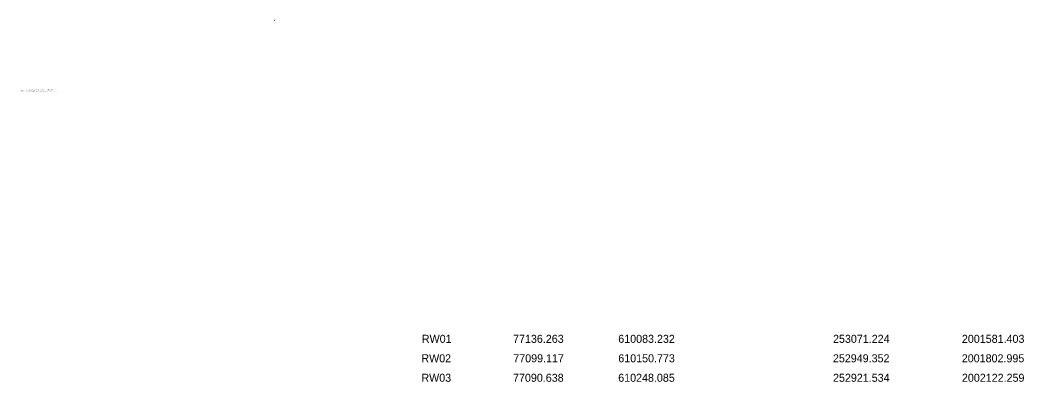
# Model space of a CAD drawing. Extents: x -4451 to 6119, y -1533 to 848.
# Drawn here: x 701 to 6119, y -1533 to 417 of the extents above; entities that cross this region are included whole.
import ezdxf

# ---------------------------------------------------------------- set-up
doc = ezdxf.new("R2010")
doc.units = 0
doc.layers.add('SC_Scratch1', color=7, linetype='Continuous')

msp = doc.modelspace()

# ---------------------------------------------------------------- linework, layer by layer
at = {"layer": 'SC_Scratch1'}
for p, q in [((2073.5, 417), (2074.5, 417)), ((2074, 417), (2076.2, 417))]:
    msp.add_line(p, q, dxfattribs=at)
msp.add_circle((2074, 417), 0.521, dxfattribs=at)

# ---------------------------------------------------------------- texts
for s, height, p in [('1', 0.0656, (2074, 417.1)), ('R/W Centerline Plat Monument Table', 0.0656, (2074.7, 417.1)), ('1:1', 0.0656, (2074.7, 416.8)), ('STATION AND OFFSET VALUES ARE REFERENCED TO THE CENTERLINE OF RIGHT-OF-WAY OR CENTERLINE OF CONSTRUCTION AS ', 2.16, (700.8, 42.8)), ('DESIGNATED BELOW:', 2.16, (700.8, 39)), ('(1) STATION AND OFFSET VALUES ARE REFERENCED TO THE EXISTING CENTERLINE OF RIGHT-OF-WAY FOR S.R. 221', 2.16, (700.8, 35.3)), ('(2) STATION AND OFFSET VALUES ARE REFERENCED TO THE PROPOSED CENTERLINE OF RIGHT OF WAY & CONSTRUCTION FOR S.R. 221', 2.16, (700.8, 31.5)), ('RW01', 43.2, (2869.2, -1322.1)), ('RW01', 43.2, (2869.2, -1322.1)), ('RW01', 43.2, (2869.2, -1322.1)), ('RW01', 43.2, (2869.2, -1322.1)), ('77136.263', 43.2, (3361.6, -1322.1)), ('77136.263', 43.2, (3361.6, -1322.1)), ('77136.263', 43.2, (3361.6, -1322.1)), ('77136.263', 43.2, (3361.6, -1322.1)), ('610083.232', 43.2, (3929.3, -1322.1)), ('610083.232', 43.2, (3929.3, -1322.1)), ('610083.232', 43.2, (3929.3, -1322.1)), ('610083.232', 43.2, (3929.3, -1322.1)), ('253071.224', 43.2, (5088.3, -1322.1)), ('253071.224', 43.2, (5088.3, -1322.1)), ('253071.224', 43.2, (5088.3, -1322.1)), ('253071.224', 43.2, (5088.3, -1322.1)), ('2001581.403', 43.2, (5783.8, -1322.1)), ('2001581.403', 43.2, (5783.8, -1322.1)), ('2001581.403', 43.2, (5783.8, -1322.1)), ('2001581.403', 43.2, (5783.8, -1322.1)), ('RW02', 43.2, (2866.7, -1427)), ('RW02', 43.2, (2866.7, -1427)), ('RW02', 43.2, (2866.7, -1427)), ('RW02', 43.2, (2866.7, -1427)), ('77099.117', 43.2, (3362.7, -1427)), ('77099.117', 43.2, (3362.7, -1427)), ('77099.117', 43.2, (3362.7, -1427)), ('77099.117', 43.2, (3362.7, -1427)), ('610150.773', 43.2, (3929.4, -1427)), ('610150.773', 43.2, (3929.4, -1427)), ('610150.773', 43.2, (3929.4, -1427)), ('610150.773', 43.2, (3929.4, -1427)), ('252949.352', 43.2, (5087.7, -1427)), ('252949.352', 43.2, (5087.7, -1427)), ('252949.352', 43.2, (5087.7, -1427)), ('252949.352', 43.2, (5087.7, -1427)), ('2001802.995', 43.2, (5783.3, -1427)), ('2001802.995', 43.2, (5783.3, -1427)), ('2001802.995', 43.2, (5783.3, -1427)), ('2001802.995', 43.2, (5783.3, -1427)), ('RW03', 43.2, (2866.8, -1532)), ('RW03', 43.2, (2866.8, -1532)), ('RW03', 43.2, (2866.8, -1532)), ('RW03', 43.2, (2866.8, -1532)), ('77090.638', 43.2, (3361.4, -1532)), ('77090.638', 43.2, (3361.4, -1532)), ('77090.638', 43.2, (3361.4, -1532)), ('77090.638', 43.2, (3361.4, -1532)), ('610248.085', 43.2, (3929, -1532)), ('610248.085', 43.2, (3929, -1532)), ('610248.085', 43.2, (3929, -1532)), ('610248.085', 43.2, (3929, -1532)), ('252921.534', 43.2, (5088.3, -1532)), ('252921.534', 43.2, (5088.3, -1532)), ('252921.534', 43.2, (5088.3, -1532)), ('252921.534', 43.2, (5088.3, -1532)), ('2002122.259', 43.2, (5783.9, -1532)), ('2002122.259', 43.2, (5783.9, -1532)), ('2002122.259', 43.2, (5783.9, -1532)), ('2002122.259', 43.2, (5783.9, -1532))]:
    msp.add_text(s, height=height, dxfattribs=at).set_placement(p)

doc.saveas('drawing.dxf')
